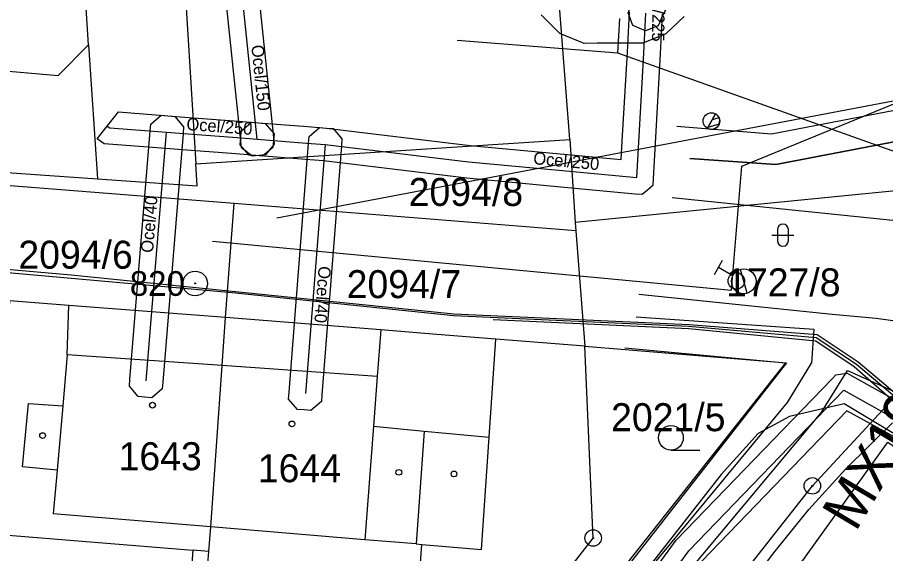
# Model space of a CAD drawing. Extents: x -781083 to -763634, y -1029516 to -1022695.
# Drawn here: x -765004.1 to -764951.3, y -1023785.5 to -1023752.9 of the extents above; entities that cross this region are included whole.
import ezdxf

# ---------------------------------------------------------------- set-up
doc = ezdxf.new("R2010")
doc.units = 0
for name, color, linetype in [('CETIN_nezaměřený', 7, 'Continuous'), ('GasNet_ochr. pásmo', 7, 'Continuous'), ('GasNet_plyn NTL', 7, 'Continuous'), ('GasNet_plyn STL', 7, 'Continuous'), ('Hranice parcel', 7, 'Continuous'), ('Parcelní čísla', 7, 'Continuous'), ('SO128401_EOV_popisky', 7, 'Continuous'), ('SSlaný_vodovod', 7, 'Continuous'), ('SVAS_kanalizace', 7, 'Continuous'), ('Vnitřní kresba', 7, 'Continuous'), ('Vrstva 17', 7, 'Continuous'), ('Vrstva 23', 7, 'Continuous'), ('Vrstva 36', 7, 'Continuous'), ('Vrstva 41', 7, 'Continuous'), ('Vrstva 49', 7, 'Continuous'), ('Vrstva 51', 7, 'Continuous'), ('Značky bodu BP', 7, 'Continuous'), ('Značky budov', 7, 'Continuous'), ('Značky kultur', 7, 'Continuous'), ('ČEZd_VN_podzemní', 7, 'Continuous')]:
    doc.layers.add(name, color=color, linetype=linetype)

# ---------------------------------------------------------------- blocks, each defined once
blk = doc.blocks.new('4.02')
at = {"layer": 'Značky budov'}
blk.add_circle((-0.07, 0.01), 1.75, dxfattribs=at)
blk = doc.blocks.new('3.04')
at = {"layer": 'Značky kultur'}
blk.add_line((0.07, 0), (17.57, 0), dxfattribs=at)
blk.add_circle((0.07, 7.5), 7.5, dxfattribs=at)
blk = doc.blocks.new('3.16')
at = {"layer": 'Značky kultur'}
for p, q in [((-6.71, 6.69), (6.71, 6.69)), ((-3.35, 10.05), (-3.35, 3.34)), ((3.35, 3.34), (3.35, 10.05))]:
    blk.add_line(p, q, dxfattribs=at)
for centre, start, end in [((0, 10.04), 0, 180), ((0, 3.34), 180, 359.9879)]:
    blk.add_arc(centre, 3.35, start, end, dxfattribs=at)
blk = doc.blocks.new('1.01')
at = {"layer": 'Značky bodu BP'}
for radius in [7.5, 0.3]:
    blk.add_circle((0, 0), radius, dxfattribs=at)
blk = doc.blocks.new('1.05')
at = {"layer": 'Značky bodu BP'}
for radius in [5, 0.303]:
    blk.add_circle((0, 0), radius, dxfattribs=at)
blk = doc.blocks.new('C724_8')
at = {"layer": 'Vrstva 36'}
for p, q in [((-5.03, 0), (5.03, 0)), ((5.03, 0), (-5.03, 0)), ((0.63, -4.98), (-4.34, -0.01)), ((3.98, -3.02), (0.96, 0))]:
    blk.add_line(p, q, dxfattribs=at)
blk.add_lwpolyline([(-5.03, 0), (5.03, 0)], dxfattribs=at)
blk.add_circle((0, 0), 5.03, dxfattribs=at)
blk.add_arc((0, 0), 5.03, 179.9939, 359.9939, dxfattribs=at)
blk.add_arc((0, 0), 5.03, 179.9939, 359.9939, dxfattribs=at)
blk = doc.blocks.new('C129')
at = {"layer": 'Vrstva 41'}
for p, q in [((-5, 17.59), (5, 17.59)), ((0, 17.59), (0, 7.51)), ((-5.31, -5.31), (5.31, 5.3))]:
    blk.add_line(p, q, dxfattribs=at)
blk.add_circle((0, 0.01), 7.5, dxfattribs=at)
blk = doc.blocks.new('C130_3')
at = {"layer": 'Vrstva 41'}
blk.add_circle((0, 0), 5, dxfattribs=at)

msp = doc.modelspace()

# ---------------------------------------------------------------- linework, layer by layer
at = {"layer": 'CETIN_nezaměřený'}
for points in [[(-764967.59, -1023755.108), (-764967.465, -1023753.005)], [(-764967.59, -1023755.108), (-764977.361, -1023754.337)], [(-764934.518, -1023776.231), (-764940.663, -1023774.809), (-764938.125, -1023765.59), (-764967.59, -1023755.108)]]:
    msp.add_lwpolyline(points, dxfattribs=at)
at = {"layer": 'GasNet_ochr. pásmo'}
for points in [[(-764991.526, -1023750.569), (-764989.747, -1023748.321), (-764988.517, -1023760.224), (-764988.475, -1023760.636), (-764988.997, -1023761.279), (-764989.409, -1023761.322), (-764989.821, -1023761.364), (-764990.464, -1023760.842), (-764990.507, -1023760.43)], [(-764966.697, -1023752.028), (-764966.68, -1023750.754), (-764967.01, -1023750.341), (-764966.964, -1023749.929), (-764966.918, -1023749.517), (-764966.271, -1023749), (-764965.859, -1023749.046), (-764965.637, -1023749.071), (-764965.592, -1023749.076), (-764965.244, -1023749.114), (-764964.747, -1023749.607), (-764964.707, -1023749.955), (-764964.669, -1023750.284), (-764964.68, -1023750.778), (-764964.703, -1023752.472), (-764964.969, -1023753.061), (-764964.974, -1023753.071), (-764965.14, -1023753.45), (-764965.912, -1023753.752), (-764966.291, -1023753.586), (-764966.67, -1023753.42), (-764966.972, -1023752.648), (-764966.806, -1023752.269), (-764966.797, -1023752.247)], [(-764998.799, -1023760.611), (-764999.238, -1023760.314), (-764997.938, -1023758.671), (-764994.935, -1023758.904), (-764993.634, -1023759.003), (-764990.639, -1023759.23), (-764989.429, -1023759.33), (-764989.016, -1023759.364), (-764988.481, -1023759.997), (-764988.515, -1023760.41), (-764988.549, -1023760.823), (-764989.182, -1023761.358), (-764989.595, -1023761.324), (-764990.797, -1023761.224), (-764993.786, -1023760.997), (-764995.089, -1023760.898)], [(-764997.276, -1023775.327), (-764997.242, -1023774.914), (-764996.009, -1023759.82), (-764995.975, -1023759.407), (-764995.344, -1023758.87), (-764994.931, -1023758.904), (-764994.518, -1023758.938), (-764993.981, -1023759.569), (-764994.015, -1023759.982), (-764995.248, -1023775.076), (-764995.282, -1023775.489), (-764995.913, -1023776.026), (-764996.326, -1023775.992), (-764996.739, -1023775.958)], [(-764984.355, -1023760.312), (-764984.387, -1023760.725), (-764985.576, -1023775.851), (-764985.608, -1023776.264), (-764986.238, -1023776.802), (-764986.651, -1023776.77), (-764987.064, -1023776.738), (-764987.602, -1023776.108), (-764987.57, -1023775.695), (-764986.381, -1023760.569), (-764986.349, -1023760.156), (-764985.719, -1023759.618), (-764985.306, -1023759.65), (-764984.893, -1023759.682)]]:
    msp.add_lwpolyline(points, close=True, dxfattribs=at)
for points in [[(-764964.891, -1023752.72), (-764965.012, -1023755.146), (-764965.325, -1023760.564), (-764965.441, -1023762.714), (-764965.465, -1023763.139), (-764965.787, -1023763.417), (-764966.109, -1023763.695), (-764966.533, -1023763.656), (-764971.278, -1023763.211), (-764976.777, -1023762.694), (-764985.483, -1023761.642), (-764986.58, -1023761.556), (-764989.589, -1023761.324), (-764990.002, -1023761.292), (-764990.541, -1023760.663), (-764990.509, -1023760.25), (-764990.477, -1023759.837), (-764989.848, -1023759.298), (-764989.435, -1023759.33), (-764986.424, -1023759.562), (-764985.285, -1023759.652), (-764976.563, -1023760.706), (-764971.092, -1023761.219), (-764967.382, -1023761.567), (-764967.321, -1023760.452), (-764967.01, -1023755.038), (-764966.889, -1023752.62)], [(-764963.56, -1023752.878), (-764964.665, -1023753.921), (-764966.077, -1023754.487), (-764966.837, -1023754.491), (-764968.488, -1023754.5), (-764968.844, -1023754.502), (-764969.643, -1023754.506), (-764971.123, -1023753.9), (-764971.689, -1023753.336), (-764972.255, -1023752.772)], [(-765004.735, -1023844.204), (-764987.098, -1023816.295), (-764964.047, -1023784.681), (-764954.572, -1023774.882), (-764954.336, -1023774.638), (-764953.664, -1023774.538), (-764953.368, -1023774.703), (-764949.815, -1023776.676), (-764944.807, -1023779.62), (-764944.555, -1023779.767), (-764928.407, -1023789.665)], [(-764926.927, -1023792.918), (-764945.583, -1023781.483), (-764945.819, -1023781.344), (-764950.807, -1023778.412), (-764953.668, -1023776.824), (-764962.513, -1023785.971), (-764985.442, -1023817.419), (-765003.137, -1023845.42), (-765021.725, -1023865.911)]]:
    msp.add_lwpolyline(points, dxfattribs=at)
at = {"layer": 'GasNet_plyn NTL'}
for p, q in [((-764989.512, -1023760.327), (-764990.636, -1023749.445)), ((-764996.245, -1023774.995), (-764995.012, -1023759.901)), ((-764985.384, -1023760.647), (-764986.573, -1023775.773))]:
    msp.add_line(p, q, dxfattribs=at)
for points in [[(-764989.512, -1023760.327), (-764986.502, -1023760.559), (-764985.384, -1023760.647), (-764976.67, -1023761.7), (-764971.185, -1023762.215), (-764966.44, -1023762.66), (-764966.323, -1023760.508), (-764966.011, -1023755.092), (-764965.89, -1023752.67)], [(-764998.616, -1023759.527), (-764998.458, -1023759.634), (-764995.012, -1023759.901), (-764993.71, -1023760), (-764990.718, -1023760.227), (-764989.512, -1023760.327)]]:
    msp.add_lwpolyline(points, dxfattribs=at)
at = {"layer": 'GasNet_plyn STL'}
msp.add_lwpolyline([(-765056.262, -1023868.365), (-765056.064, -1023868.32), (-765055.22, -1023868.128), (-765047.384, -1023866.918), (-765047.344, -1023866.915), (-765022.199, -1023864.945), (-765003.936, -1023844.812), (-764986.27, -1023816.857), (-764963.28, -1023785.326), (-764953.853, -1023775.577), (-764950.311, -1023777.544), (-764945.313, -1023780.482), (-764945.069, -1023780.625), (-764927.667, -1023791.291)], dxfattribs=at)
at = {"layer": 'Hranice parcel'}
for p, q in [((-764970.5, -1023760.34), (-764972.31, -1023737.27)), ((-764999.76, -1023754.6), (-765000.543, -1023742.51)), ((-764999.76, -1023754.6), (-764999.22, -1023762.73)), ((-764993.24, -1023761.83), (-764970.5, -1023760.34)), ((-764970.5, -1023760.34), (-764970.19, -1023765.39)), ((-765008.75, -1023762.07), (-764999.22, -1023762.73)), ((-764934.22, -1023761.84), (-764970.19, -1023765.39)), ((-764990.9, -1023764.24), (-765008.8, -1023762.81)), ((-764991.43, -1023771.15), (-764990.9, -1023764.24)), ((-764970.15, -1023765.89), (-764990.9, -1023764.24)), ((-764970.19, -1023765.39), (-764970.15, -1023765.89)), ((-764970.15, -1023765.89), (-764969.6, -1023772.89)), ((-764969.6, -1023772.89), (-764975, -1023772.47))]:
    msp.add_line(p, q, dxfattribs=at)
for points in [[(-764994.23, -1023745.79), (-764993.24, -1023761.83)], [(-765009.93, -1023755.72), (-765001.6, -1023756.46), (-764999.76, -1023754.6)], [(-764999.22, -1023762.73), (-764993.16, -1023763.15), (-764993.24, -1023761.83)], [(-765004.56, -1023770.15), (-765005.38, -1023784.31), (-764993.41, -1023785.29), (-764993.66, -1023788.64), (-764992.71, -1023788.71)], [(-764991.43, -1023771.15), (-765000.96, -1023770.42), (-765004.56, -1023770.15)], [(-764992.56, -1023786.82), (-764992.45, -1023785.37), (-764992.33, -1023783.87), (-764991.64, -1023774.08), (-764991.43, -1023771.15)], [(-764975, -1023772.47), (-764978.58, -1023772.19), (-764982, -1023771.91), (-764991.43, -1023771.15)], [(-764992.56, -1023786.82), (-764981.56, -1023787.6), (-764979.6, -1023786.33), (-764979.5, -1023784.94), (-764975.87, -1023785.24), (-764975.41, -1023778.43), (-764975, -1023772.47)], [(-764986.64, -1023807.05), (-764984.91, -1023804.83), (-764969.09, -1023784.55), (-764969.6, -1023772.89)], [(-764969.6, -1023772.89), (-764957.34, -1023773.9), (-764973.13, -1023794.09), (-764983.68, -1023810.31)], [(-764978.77, -1023810.6), (-764955.77, -1023781.38), (-764950.74, -1023775.95), (-764945.55, -1023773.21), (-764940.98, -1023772.86)]]:
    msp.add_lwpolyline(points, dxfattribs=at)
at = {"layer": 'SSlaný_vodovod'}
msp.add_lwpolyline([(-764992.228, -1023766.529), (-764960.68, -1023769.5), (-764960.051, -1023761.959), (-764942.62, -1023754.819), (-764923.92, -1023735.658)], dxfattribs=at)
at = {"layer": 'SVAS_kanalizace'}
msp.add_lwpolyline([(-764988.323, -1023765.095), (-764936.562, -1023755.29), (-764937.881, -1023728.404)], dxfattribs=at)
at = {"layer": 'Vnitřní kresba'}
for p, q in [((-765001.05, -1023773.43), (-765000.96, -1023770.42)), ((-764982, -1023771.91), (-764982.21, -1023774.73)), ((-765001.05, -1023773.43), (-765001.32, -1023776.53)), ((-764991.64, -1023774.08), (-765001.05, -1023773.43)), ((-764982.21, -1023774.73), (-764991.64, -1023774.08)), ((-764982.21, -1023774.73), (-764982.44, -1023777.75)), ((-765003.77, -1023780.22), (-765003.41, -1023776.38)), ((-765003.41, -1023776.38), (-765001.32, -1023776.53)), ((-765001.32, -1023776.53), (-765001.67, -1023780.42)), ((-764982.44, -1023777.75), (-764982.96, -1023784.65)), ((-764982.44, -1023777.75), (-764979.36, -1023778.05)), ((-764979.36, -1023778.05), (-764979.85, -1023784.91)), ((-764979.36, -1023778.05), (-764975.41, -1023778.43)), ((-765001.67, -1023780.42), (-765003.77, -1023780.22)), ((-765001.67, -1023780.42), (-765001.9, -1023783.07)), ((-764992.33, -1023783.87), (-765001.9, -1023783.07)), ((-764982.96, -1023784.65), (-764992.33, -1023783.87)), ((-764979.85, -1023784.91), (-764982.96, -1023784.65)), ((-764992.45, -1023785.37), (-764993.41, -1023785.29)), ((-764979.85, -1023784.91), (-764979.5, -1023784.94))]:
    msp.add_line(p, q, dxfattribs=at)
at = {"layer": 'Vrstva 17'}
for points in [[(-764967.173, -1023772.995), (-764957.403, -1023773.908), (-764973.218, -1023793.881)], [(-764962.354, -1023791.081), (-764958.112, -1023785.44), (-764955.981, -1023782.82), (-764953.732, -1023780.351), (-764950.895, -1023777.549)]]:
    msp.add_lwpolyline(points, dxfattribs=at)
at = {"layer": 'Vrstva 23'}
msp.add_lwpolyline([(-764955, -1023794.4), (-764959.98, -1023790.954), (-764951.178, -1023778.731), (-764946.17, -1023782.181), (-764955, -1023794.4)], dxfattribs=at)
at = {"layer": 'Vrstva 49'}
for points in [[(-764948.818, -1023760.122), (-764950.495, -1023760.418), (-764957.987, -1023761.854), (-764963.217, -1023761.495)], [(-764950.888, -1023765.258), (-764964.287, -1023763.89)]]:
    msp.add_lwpolyline(points, dxfattribs=at)
at = {"layer": 'Vrstva 51'}
for points in [[(-764936.174, -1023737.647), (-764926.665, -1023752.349), (-764927.806, -1023754.266), (-764946.873, -1023757.862), (-764949.207, -1023758.283), (-764958.243, -1023760.019), (-764964.009, -1023759.557)], [(-764963.217, -1023761.495), (-764957.987, -1023761.854), (-764950.495, -1023760.418)], [(-764929.467, -1023769.83), (-764933.947, -1023767.769), (-764940.49, -1023766.769), (-764949.327, -1023765.563), (-764950.888, -1023765.258), (-764964.287, -1023763.89)], [(-764966.319, -1023769.737), (-764954.558, -1023770.962), (-764951.901, -1023771.205), (-764946.827, -1023771.9), (-764934.698, -1023774.865), (-764932.987, -1023774.749), (-764931.793, -1023775.562), (-764930.784, -1023776.541), (-764929.553, -1023777.292)], [(-764966.485, -1023771.106), (-764955.671, -1023771.867), (-764955.814, -1023773.93)], [(-764965.956, -1023786.782), (-764957.275, -1023776.311), (-764955.814, -1023773.93)], [(-764964.48, -1023788.003), (-764955.24, -1023776.938), (-764953.637, -1023774.372), (-764949.357, -1023776.288)]]:
    msp.add_lwpolyline(points, dxfattribs=at)
at = {"layer": 'ČEZd_VN_podzemní'}
for points in [[(-765026.02, -1023766.606), (-765017.64, -1023767.27), (-764991.02, -1023769.64), (-764977.58, -1023771.04), (-764963.3, -1023771.68), (-764955.53, -1023772.37), (-764953.09, -1023773.98), (-764950.24, -1023776.4), (-764941.82, -1023783.22), (-764932.1, -1023789.3), (-764920.89, -1023797.93), (-764920.39, -1023798.28), (-764919.26, -1023802.09), (-764917.991, -1023810.215)], [(-765025.985, -1023766.54), (-765017.58, -1023767.08), (-765000.81, -1023768.56), (-764991.02, -1023769.56), (-764977.55, -1023770.93), (-764963.25, -1023771.59), (-764955.48, -1023772.18), (-764952.98, -1023773.85), (-764950.27, -1023776.13), (-764941.79, -1023783.16), (-764931.46, -1023789.61), (-764926.79, -1023793.218)], [(-764975.165, -1023771.272), (-764963.27, -1023771.83), (-764955.56, -1023772.57), (-764953.23, -1023774.14), (-764950.4, -1023776.63), (-764941.75, -1023783.49), (-764932.23, -1023789.6), (-764920.91, -1023798.1), (-764919.41, -1023802.11), (-764917.991, -1023810.215)], [(-764917.991, -1023810.215), (-764918.562, -1023807.51), (-764919.66, -1023802.13), (-764920.94, -1023798.44), (-764932.4, -1023789.85), (-764941.94, -1023783.52), (-764953.83, -1023776.39), (-764957.16, -1023777.16), (-764959.07, -1023778.2), (-764961.32, -1023780.7), (-764970.6, -1023792.56), (-764976.55, -1023801.37), (-764982.69, -1023810.79), (-764988.88, -1023820.11), (-764995.81, -1023830.85), (-765001.33, -1023839.24), (-765010.71, -1023850.19)]]:
    msp.add_lwpolyline(points, dxfattribs=at)

# ---------------------------------------------------------------- block references
at = {"layer": 'Vrstva 36', "xscale": 0.09999999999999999, "yscale": 0.09999999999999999, "rotation": 61.00178559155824}
msp.add_blockref('C724_8', (-764961.903, -1023759.226), dxfattribs=at)
at = {"layer": 'Vrstva 41', "rotation": 61.00178559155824}
for name, p, xscale, yscale in [('C129', (-764959.937, -1023768.959), 0.09999999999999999, 0.09999999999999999), ('C130_3', (-764960.392, -1023768.931), 0.10000000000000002, 0.10000000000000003)]:
    msp.add_blockref(name, p, dxfattribs=dict(at, xscale=xscale, yscale=yscale))
at = {"layer": 'Značky bodu BP', "xscale": 0.1, "yscale": 0.10000000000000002}
for name, p in [('1.01', (-764993.28, -1023769.09)), ('1.05', (-764955.77, -1023781.38)), ('1.05', (-764969.09, -1023784.55))]:
    msp.add_blockref(name, p, dxfattribs=at)
at = {"layer": 'Značky budov', "xscale": 0.1, "yscale": 0.10000000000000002}
for p in [(-764995.86, -1023776.48), (-764987.39, -1023777.62), (-765002.54, -1023778.33), (-764980.89, -1023780.56), (-764977.54, -1023780.66)]:
    msp.add_blockref('4.02', p, dxfattribs=at)
at = {"layer": 'Značky kultur', "xscale": 0.1, "yscale": 0.10000000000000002}
for name, p in [('3.16', (-764957.56, -1023766.82)), ('3.04', (-764964.37, -1023779.21))]:
    msp.add_blockref(name, p, dxfattribs=at)

# ---------------------------------------------------------------- texts
at = {"layer": 'GasNet_plyn NTL'}
for s, rotation, p in [('PE/225', 269.231, (-764965.475, -1023751.104)), ('Ocel/150', 275.8979, (-764989.867, -1023754.635)), ('Ocel/250', 355.6518, (-764993.829, -1023759.763)), ('Ocel/250', 354.6361, (-764972.754, -1023761.836)), ('Ocel/40', 85.33, (-764995.841, -1023767.247)), ('Ocel/40', 265.5054, (-764985.766, -1023768.011))]:
    msp.add_text(s, height=0.75, rotation=rotation, dxfattribs=at).set_placement(p)
at = {"layer": 'Parcelní čísla'}
for s, p in [('2094/8', (-764980.3, -1023764.38)), ('2094/6', (-765004.02, -1023768.19)), ('2094/7', (-764984.07, -1023769.98)), ('1727/8', (-764961.01, -1023769.87)), ('2021/5', (-764968, -1023778.06)), ('1643', (-764997.93, -1023780.43)), ('1644', (-764989.47, -1023781.16))]:
    msp.add_text(s, height=1.7, dxfattribs=at).set_placement(p)
at = {"layer": 'SO128401_EOV_popisky'}
msp.add_text('MX19.1', height=2.5, rotation=59.2569, dxfattribs=at).set_placement((-764953.139, -1023784.224))
at = {"layer": 'Značky bodu BP'}
msp.add_text('820', height=1.5, dxfattribs=at).set_placement((-764997.248, -1023769.84))

doc.saveas('drawing.dxf')
